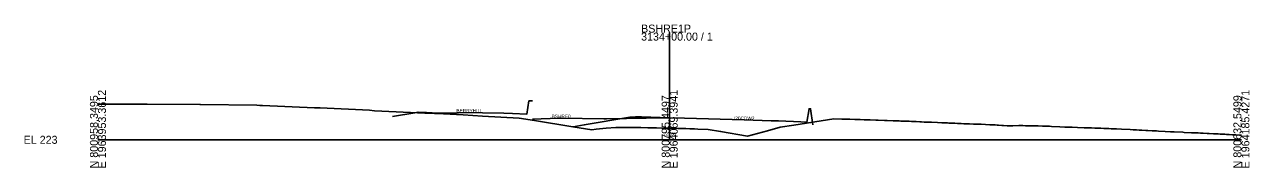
# Model space of a CAD drawing. Extents: x -26 to 403, y -10 to 6039.
# Drawn here: x -25.7 to 402.8, y 5490.3 to 5540.4 of the extents above; entities that cross this region are included whole.
import ezdxf

# ---------------------------------------------------------------- set-up
doc = ezdxf.new("R2010")
doc.units = 0
for name, color, linetype in [('Default', 7, 'Continuous'), ('RD_GPK_XS_Cell', 7, 'Continuous'), ('RD_TX_Misc1', 7, 'Continuous'), ('RD_XS_ExGround', 7, 'Continuous'), ('RD_XS_Pave', 7, 'Continuous'), ('RD_XS_TX_Elev_EX', 7, 'Continuous')]:
    doc.layers.add(name, color=color, linetype=linetype)

msp = doc.modelspace()

# ---------------------------------------------------------------- linework, layer by layer
at = {"layer": 'RD_GPK_XS_Cell'}
for p, q in [((200, 5500), (200, 5537.52)), ((0, 5500), (200, 5500)), ((200, 5500), (400, 5500))]:
    msp.add_line(p, q, dxfattribs=at)
at = {"layer": 'RD_XS_ExGround'}
msp.add_lwpolyline([(0, 5512.51), (15.75, 5512.46), (17.24, 5512.43), (35.59, 5512.39), (35.91, 5512.39), (55.61, 5512.08), (56.62, 5512.04), (57.06, 5512.05), (57.56, 5512.04), (75.79, 5511.23), (77.79, 5511.17), (95.04, 5510.41), (96.77, 5510.18), (114.37, 5509.37), (115.97, 5509.31), (116.97, 5509.27), (117.71, 5509.24), (118.18, 5509.22), (118.53, 5509.21), (127.71, 5508.71), (134.5, 5508.32), (147.31, 5507.62), (152.71, 5506.77), (166.1, 5504.55), (172.76, 5503.53), (174.26, 5503.69), (177.83, 5504.05), (181.14, 5504.27), (184.87, 5504.32), (185.63, 5504.29), (186.3, 5504.31), (186.68, 5504.3), (187.03, 5504.28), (187.55, 5504.28), (189.29, 5504.27), (189.88, 5504.26), (192.35, 5504.22), (194.19, 5504.19), (195.38, 5504.16), (197.26, 5504.13), (198.03, 5504.11), (198.49, 5504.11), (200, 5504.08), (201.45, 5504.04), (202.82, 5504.01), (203.81, 5503.99), (204.55, 5503.97), (205.62, 5503.94), (207.07, 5503.9), (207.61, 5503.88), (208.64, 5503.84), (209.89, 5503.78), (213.52, 5503.65), (217.79, 5502.95), (227.28, 5501.32), (234.24, 5503.19), (238.71, 5504.39), (243.43, 5505.13), (257.47, 5507.33), (260.21, 5507.25), (260.58, 5507.25), (263.05, 5507.19), (264.78, 5507.13), (266.05, 5507.09), (266.68, 5507.06), (267.99, 5507.01), (269.01, 5506.98), (270.17, 5506.94), (272.18, 5506.88), (272.9, 5506.85), (275.19, 5506.77), (275.54, 5506.76), (276.11, 5506.74), (278.23, 5506.65), (280.27, 5506.59), (280.91, 5506.58), (281.35, 5506.56), (283.74, 5506.47), (284.58, 5506.44), (286.26, 5506.36), (287.46, 5506.3), (288.14, 5506.27), (289.06, 5506.23), (290.52, 5506.17), (291.6, 5506.12), (293.65, 5506.04), (295.23, 5505.98), (296.7, 5505.92), (297.15, 5505.9), (297.71, 5505.88), (299.75, 5505.79), (300.64, 5505.75), (302.03, 5505.68), (302.87, 5505.65), (304.92, 5505.57), (306.28, 5505.52), (308.96, 5505.42), (310.48, 5505.35), (311.97, 5505.29), (313.05, 5505.25), (313.84, 5505.23), (314.56, 5505.17), (315.05, 5505.13), (316.16, 5505.01), (316.47, 5504.99), (316.82, 5504.98), (318.1, 5504.9), (319.74, 5504.85), (320.07, 5504.87), (322.2, 5505.02), (322.62, 5505.05), (323.51, 5504.98), (324.48, 5504.94), (325.52, 5504.88), (325.91, 5504.87), (326.24, 5504.94), (326.71, 5504.93), (327.66, 5504.92), (328.4, 5504.92), (328.86, 5504.9), (330.45, 5504.82), (332.01, 5504.75), (332.92, 5504.72), (333.53, 5504.69), (336.49, 5504.56), (338.24, 5504.48), (339.64, 5504.42), (340.12, 5504.4), (340.8, 5504.37), (342.72, 5504.32), (344.99, 5504.24), (345.46, 5504.23), (345.76, 5504.22), (347.61, 5504.15), (348.74, 5504.11), (349.18, 5504.1), (350.79, 5504.04), (351.92, 5503.98), (352.6, 5503.95), (353.64, 5503.91), (354.44, 5503.88), (354.99, 5503.86), (356.3, 5503.81), (358.1, 5503.73), (361.13, 5503.59), (362.11, 5503.53), (363.32, 5503.46), (364.2, 5503.41), (365.15, 5503.37), (366.55, 5503.3), (367.25, 5503.26), (368.79, 5503.18), (370.31, 5503.11), (371.01, 5503.07), (373.38, 5502.94), (375.17, 5502.83), (376.45, 5502.77), (379.51, 5502.63), (380.04, 5502.61), (382.6, 5502.49), (383.02, 5502.47), (383.63, 5502.44), (384.85, 5502.39), (385.68, 5502.35), (386.65, 5502.3), (388.02, 5502.23), (388.73, 5502.19), (390.24, 5502.12), (391.89, 5502.04), (392.63, 5502.01), (393.59, 5501.97), (394.22, 5501.94), (394.82, 5501.9), (395.71, 5501.86), (396.92, 5501.8), (397.58, 5501.77), (398.07, 5501.74), (399.32, 5501.67), (400, 5501.63)], dxfattribs=at)
at = {"layer": 'RD_XS_Pave'}
for points in [[(103, 5508.18), (110.86, 5509.49), (111.98, 5509.68), (113.9, 5509.61), (114.98, 5509.58), (116.9, 5509.39), (117.98, 5509.28), (122.37, 5509.37), (129.99, 5509.52), (134.47, 5509.44), (142, 5509.29), (145.04, 5509.17), (150, 5508.97), (150.75, 5513.64), (151.23, 5513.64), (152, 5513.64)], [(151.96, 5507.22), (161.2, 5507.6), (161.96, 5507.63), (176.92, 5507.35), (177.96, 5507.33), (198.82, 5507.68), (200, 5507.7), (200, 5507.7)], [(166.3, 5504.59), (170.14, 5505.23), (186.01, 5507.89), (186.36, 5507.92), (188.01, 5508.05), (190.14, 5507.99), (200, 5507.7), (200, 5507.7), (205.2, 5507.55), (226.03, 5506.94), (235.54, 5506.67), (238.03, 5506.59), (245.89, 5506.29), (248.04, 5506.2), (248.79, 5510.87), (249.29, 5510.87), (250.04, 5505.2)]]:
    msp.add_lwpolyline(points, dxfattribs=at)

# ---------------------------------------------------------------- texts
at = {"layer": 'Default'}
msp.add_text('-', height=0.0001, dxfattribs=at).set_placement((0, 5500))
at = {"layer": 'RD_GPK_XS_Cell'}
for s, p in [('3134+00.00 / 1', (190, 5534.72)), ('BSHRE1P', (190, 5537.52)), ('EL 223', (-26, 5498.6))]:
    msp.add_text(s, height=2.8, dxfattribs=at).set_placement(p)
for s, p in [('N 800958.3495', (0, 5490)), ('E 1963953.3612', (2.8, 5490)), ('N 800795.4497', (200, 5490)), ('E 1964069.3941', (202.8, 5490)), ('N 800632.5499', (400, 5490)), ('E 1964185.4271', (402.8, 5490))]:
    msp.add_text(s, height=2.8, rotation=90, dxfattribs=at).set_placement(p)
at = {"layer": 'RD_TX_Misc1'}
for s, p in [('BERRYHILL', (125.41, 5509.58)), ('BSHRE0', (158.71, 5507.63)), ('I20CDW2', (222.49, 5506.94))]:
    msp.add_text(s, height=1.2, dxfattribs=at).set_placement(p)
at = {"layer": 'RD_XS_TX_Elev_EX'}
msp.add_text('227.08', height=1, dxfattribs=at).set_placement((197.9, 5501.58))

doc.saveas('drawing.dxf')
